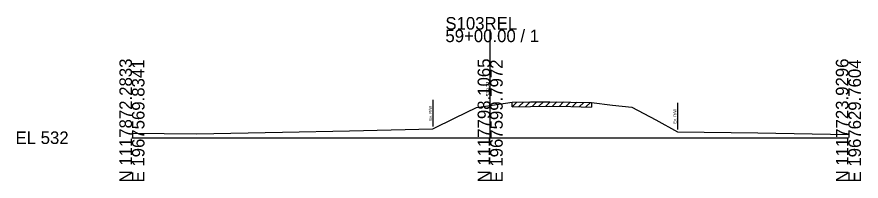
# Model space of a CAD drawing. Extents: x -26 to 163, y -10 to 24518.
# Drawn here: x -25.7 to 162.8, y 9490.3 to 9527 of the extents above; entities that cross this region are included whole.
import ezdxf

# ---------------------------------------------------------------- set-up
doc = ezdxf.new("R2010")
doc.units = 0
for name, color, linetype in [('RD_GPK_XS_Cell', 7, 'Continuous'), ('RD_XS_ExGround', 7, 'Continuous'), ('RD_XS_ExPaveRet', 7, 'Continuous'), ('RD_XS_ExRW', 7, 'Continuous'), ('RD_XS_TX_Elev_EX', 7, 'Continuous')]:
    doc.layers.add(name, color=color, linetype=linetype)

msp = doc.modelspace()

# ---------------------------------------------------------------- linework, layer by layer
at = {"layer": 'RD_GPK_XS_Cell'}
for p, q in [((80, 9500), (80, 9524.15)), ((0, 9500), (80, 9500)), ((80, 9500), (160, 9500))]:
    msp.add_line(p, q, dxfattribs=at)
at = {"layer": 'RD_XS_ExGround'}
msp.add_lwpolyline([(0, 9501), (14.45, 9500.9), (33.59, 9501.21), (48.58, 9501.55), (67.21, 9501.97), (72.19, 9504.42), (76.94, 9506.73), (80, 9507.21), (81.43, 9507.43), (84.9, 9507.93), (89.02, 9507.99), (93.28, 9508.05), (98.03, 9507.95), (102.61, 9507.86), (107.33, 9507.3), (111.62, 9506.85), (116.96, 9503.96), (121.83, 9501.31), (139.81, 9501.09), (160, 9500.69)], dxfattribs=at)
at = {"layer": 'RD_XS_ExPaveRet'}
for p, q in [((84.9, 9506.93), (85.92, 9507.94)), ((84.9, 9506.93), (84.9, 9507.93)), ((86.4, 9506.95), (87.42, 9507.96)), ((87.9, 9506.97), (88.92, 9507.99)), ((89.4, 9506.99), (90.42, 9508.01)), ((90.9, 9507.02), (91.92, 9508.03)), ((92.4, 9507.04), (93.41, 9508.05)), ((93.9, 9507.04), (94.88, 9508.02)), ((95.4, 9507), (96.38, 9507.98)), ((96.9, 9506.97), (97.88, 9507.95)), ((98.4, 9506.94), (99.39, 9507.92)), ((99.9, 9506.91), (100.89, 9507.9)), ((101.4, 9506.89), (102.39, 9507.87)), ((102.61, 9507.86), (102.61, 9506.86)), ((84.9, 9506.93), (89.02, 9506.99)), ((89.02, 9506.99), (93.28, 9507.05)), ((93.28, 9507.05), (98.03, 9506.95)), ((98.03, 9506.95), (102.61, 9506.86))]:
    msp.add_line(p, q, dxfattribs=at)
at = {"layer": 'RD_XS_ExRW'}
for p, q in [((67.21, 9508.47), (67.21, 9502.47)), ((67.21, 9508.47), (67.21, 9502.47)), ((121.83, 9507.81), (121.83, 9501.81)), ((121.83, 9507.81), (121.83, 9501.81))]:
    msp.add_line(p, q, dxfattribs=at)

# ---------------------------------------------------------------- texts
at = {"layer": 'RD_GPK_XS_Cell'}
for s, p in [('S103REL', (70, 9524.15)), ('59+00.00 / 1', (70, 9521.35)), ('EL 532', (-26, 9498.6))]:
    msp.add_text(s, height=2.8, dxfattribs=at).set_placement(p)
for s, p in [('N 1117872.2833', (0, 9490)), ('E 1967569.8341', (2.8, 9490)), ('N 1117798.1065', (80, 9490)), ('E 1967599.7972', (82.8, 9490)), ('N 1117723.9296', (160, 9490)), ('E 1967629.7604', (162.8, 9490))]:
    msp.add_text(s, height=2.8, rotation=90, dxfattribs=at).set_placement(p)
at = {"layer": 'RD_XS_ExRW'}
for p in [(66.96, 9503.81), (66.96, 9503.81), (121.58, 9503.15), (121.58, 9503.15)]:
    msp.add_text('Ex. R/W ', height=0.65, rotation=90, dxfattribs=at).set_placement(p)
at = {"layer": 'RD_XS_TX_Elev_EX'}
msp.add_text('539.21', height=0.8, rotation=90, dxfattribs=at).set_placement((79.9, 9509.21))

doc.saveas('drawing.dxf')
